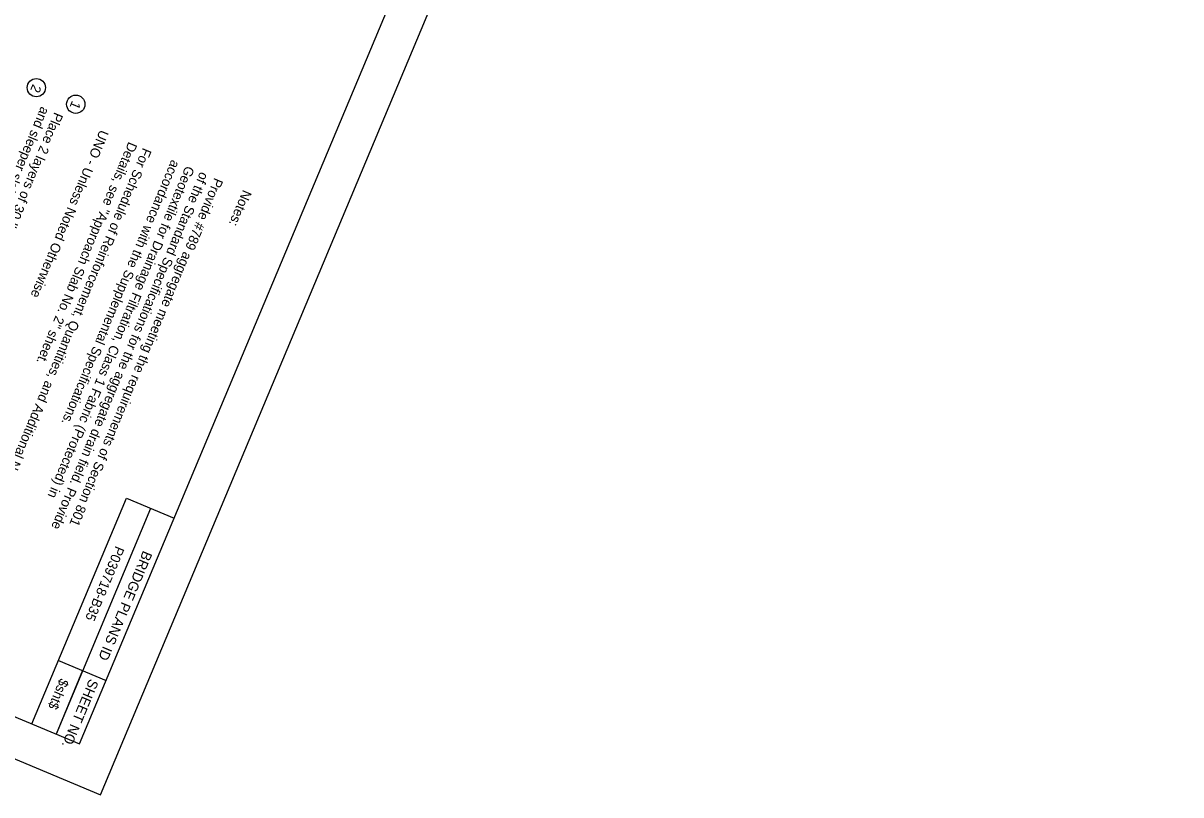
# Model space of a CAD drawing. Extents: x 1968564 to 1968711, y 796599 to 796794.
# Drawn here: x 1968641 to 1968700.7, y 796598.9 to 796638.7 of the extents above; entities that cross this region are included whole.
import ezdxf

# ---------------------------------------------------------------- set-up
doc = ezdxf.new("R2010")
doc.units = 0
for name, color, linetype in [('BR_AUTO DIMENSION', 7, 'Continuous'), ('BR_BORDER LINES', 7, 'Continuous'), ('BR_TEXT', 7, 'Continuous'), ('Level 31', 7, 'Continuous')]:
    doc.layers.add(name, color=color, linetype=linetype)

msp = doc.modelspace()

# ---------------------------------------------------------------- linework, layer by layer
at = {"layer": 'BR_AUTO DIMENSION'}
for centre in [(1968641.698, 796635.352), (1968643.731, 796634.499)]:
    msp.add_circle(centre, 0.472, dxfattribs=at)
at = {"layer": 'BR_BORDER LINES'}
for p, q in [((1968643.927, 796601.539), (1968696.012, 796725.723)), ((1968566.464, 796634.028), (1968643.927, 796601.539)), ((1968641.468, 796602.571), (1968646.345, 796614.198)), ((1968646.345, 796614.198), (1968648.804, 796613.167)), ((1968647.588, 796613.677), (1968642.711, 796602.049)), ((1968642.838, 796605.839), (1968645.298, 796604.807)), ((1968644.082, 796605.317), (1968642.711, 796602.049))]:
    msp.add_line(p, q, dxfattribs=at)
at = {"layer": 'Level 31'}
msp.add_lwpolyline([(1968619.541, 796765.748), (1968563.846, 796632.955), (1968644.997, 796598.919), (1968700.693, 796731.712)], close=True, dxfattribs=at)

# ---------------------------------------------------------------- texts
at = {"layer": 'BR_TEXT'}
for s, height, p in [('2', 0.5, (1968641.516, 796635.565)), ('1', 0.5, (1968643.549, 796634.712)), ('Place 2 layers of 30 lb. roofing felt paper between approach slab ', 0.49995, (1968642.632, 796634.12)), ('and sleeper slab.', 0.49995, (1968641.941, 796634.41)), ('UNO - Unless Noted Otherwise', 0.49995, (1968644.98, 796633.215)), ('For Schedule of Reinforcement, Quantities, and Additional Notes and ', 0.49995, (1968647.193, 796632.287)), ('Details, see "Approach Slab No. 2" sheet.', 0.49995, (1968646.455, 796632.596)), ('accordance with the Supplemental Specifications. ', 0.49995, (1968648.668, 796631.668)), ('Geotextile for Drainage Filtration, Class 1 Fabric (Protected) in ', 0.49995, (1968649.406, 796631.359)), ('of the Standard Specifications for the aggregate drain field. Provide ', 0.49995, (1968650.144, 796631.049)), ('Provide #789 aggregate meeting the requirements of Section 801 ', 0.49995, (1968650.881, 796630.74)), ('Notes:', 0.5, (1968652.357, 796630.121)), ('P039718-B35', 0.5, (1968645.789, 796611.776)), ('BRIDGE PLANS ID', 0.52, (1968647.21, 796611.532)), ('$sht$', 0.5, (1968642.927, 796604.952)), ('SHEET NO.', 0.52, (1968644.439, 796604.926))]:
    msp.add_text(s, height=height, rotation=247.24601, dxfattribs=at).set_placement(p)

doc.saveas('drawing.dxf')
